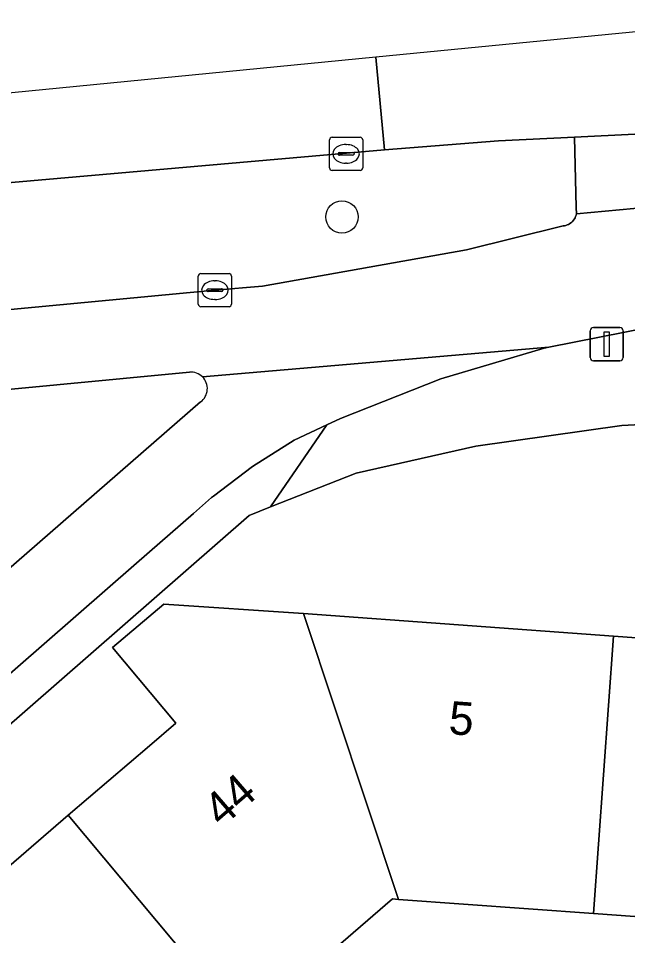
# Model space of a CAD drawing. Extents: x 160304 to 160955, y 383684 to 384161.
# Drawn here: x 160541.25 to 160559.64, y 384133.2 to 384160.88 of the extents above; entities that cross this region are included whole.
import ezdxf

# ---------------------------------------------------------------- set-up
doc = ezdxf.new("R2010")
doc.units = 0
for name, color, linetype in [('IMGEO_Boom', 7, 'Continuous'), ('IMGEO_Erf', 7, 'Continuous'), ('IMGEO_Fietspad_open', 7, 'Continuous'), ('IMGEO_Groenvoorziening', 7, 'Continuous'), ('IMGEO_Haag', 7, 'Continuous'), ('IMGEO_Kolk', 7, 'Continuous'), ('IMGEO_Lichtmast', 7, 'Continuous'), ('IMGEO_Pand', 7, 'Continuous'), ('IMGEO_Pand_nummerreeks', 7, 'Continuous'), ('IMGEO_Rijbaan_lokaal_gesloten', 7, 'Continuous'), ('IMGEO_Voetpad_open', 7, 'Continuous')]:
    doc.layers.add(name, color=color, linetype=linetype)

msp = doc.modelspace()

# ---------------------------------------------------------------- linework, layer by layer
at = {"layer": 'IMGEO_Boom'}
msp.add_circle((160551.016, 384154.889), 0.489, dxfattribs=at)
at = {"layer": 'IMGEO_Erf'}
for points in [[(160563.905, 384148.825), (160559.462, 384148.597), (160555.057, 384147.972), (160551.448, 384147.155), (160548.855, 384146.134), (160548.216, 384145.882), (160534.901, 384134.253), (160534.556, 384133.899), (160534.244, 384133.516), (160533.967, 384133.107), (160533.728, 384132.674), (160533.529, 384132.222), (160533.37, 384131.754), (160533.255, 384131.273), (160533.182, 384130.784), (160533.173, 384130.684), (160530.921, 384098.428)], [(160533.258, 384098.425), (160533.684, 384104.304), (160534.096, 384109.976), (160534.507, 384115.643), (160534.918, 384121.312), (160535.658, 384130.704), (160542.752, 384136.829), (160545.202, 384138.927), (160546.003, 384139.613), (160544.086, 384141.892), (160545.639, 384143.198), (160549.86, 384142.916), (160559.216, 384142.237), (160564.899, 384141.825)], [(160564.295, 384133.45), (160558.615, 384133.862), (160552.723, 384134.289), (160552.545, 384134.302), (160548.084, 384130.45), (160543.616, 384126.592), (160543.136, 384120.655), (160542.725, 384114.987), (160545.913, 384114.756), (160545.503, 384109.097), (160546.387, 384109.033), (160546.147, 384105.723), (160542.074, 384106.018), (160541.903, 384103.658), (160541.504, 384098.152)]]:
    msp.add_lwpolyline(points, dxfattribs=at)
at = {"layer": 'IMGEO_Fietspad_open'}
for points in [[(160561.563, 384155.305), (160558.095, 384154.984), (160558.084, 384154.94), (160558.07, 384154.901), (160558.053, 384154.864), (160558.033, 384154.828), (160558.01, 384154.794), (160557.984, 384154.763), (160557.955, 384154.734), (160557.923, 384154.708), (160557.89, 384154.684), (160557.854, 384154.664), (160557.817, 384154.647), (160557.778, 384154.633), (160557.738, 384154.623), (160557.698, 384154.617), (160557.657, 384154.614), (160554.776, 384153.901), (160548.621, 384152.802), (160547.181, 384152.679), (160508.78, 384149.051)], [(160546.806, 384150.059), (160557.264, 384150.954), (160560.321, 384151.564), (160566.689, 384152.042)], [(160547.082, 384146.416), (160547.136, 384146.461), (160548.319, 384147.36), (160549.578, 384148.15), (160550.555, 384148.612), (160550.969, 384148.808), (160554, 384150.005), (160557.125, 384150.926), (160557.264, 384150.954), (160546.806, 384150.059)], [(160509.91, 384146.721), (160509.934, 384146.724), (160546.418, 384150.201)], [(160546.75, 384149.308), (160539.384, 384142.903), (160535.894, 384139.821), (160537.481, 384138.035), (160544.813, 384144.436), (160546.533, 384145.937), (160547.082, 384146.416)]]:
    msp.add_lwpolyline(points, dxfattribs=at)
for centre, radius, start, end in [((160546.46, 384149.715), 0.488, 44.8556, 94.9413), ((160546.459, 384149.707), 0.494, 306.0545, 45.4165)]:
    msp.add_arc(centre, radius, start, end, dxfattribs=at)
at = {"layer": 'IMGEO_Groenvoorziening'}
for points in [[(160508.78, 384149.051), (160547.181, 384152.679), (160548.621, 384152.802), (160554.776, 384153.901), (160557.657, 384154.614), (160557.698, 384154.617), (160557.738, 384154.623), (160557.778, 384154.633), (160557.817, 384154.647), (160557.854, 384154.664), (160557.89, 384154.684), (160557.923, 384154.708), (160557.955, 384154.734), (160557.984, 384154.763), (160558.01, 384154.794), (160558.033, 384154.828), (160558.053, 384154.864), (160558.07, 384154.901), (160558.084, 384154.94), (160558.095, 384154.984), (160558.091, 384155.173), (160558.033, 384157.298), (160555.741, 384157.19), (160552.296, 384156.916), (160540.226, 384155.853)], [(160546.418, 384150.201), (160509.934, 384146.724), (160509.91, 384146.721)], [(160536.119, 384146.661), (160539.384, 384142.903), (160546.75, 384149.308)]]:
    msp.add_lwpolyline(points, dxfattribs=at)
for centre, radius, start, end in [((160546.46, 384149.715), 0.488, 44.8556, 94.9413), ((160546.459, 384149.707), 0.494, 306.0545, 45.4165)]:
    msp.add_arc(centre, radius, start, end, dxfattribs=at)
at = {"layer": 'IMGEO_Haag'}
msp.add_lwpolyline([(160508.78, 384149.051), (160547.181, 384152.679), (160548.621, 384152.802), (160554.776, 384153.901), (160557.657, 384154.614), (160557.698, 384154.617), (160557.738, 384154.623), (160557.778, 384154.633), (160557.817, 384154.647), (160557.854, 384154.664), (160557.89, 384154.684), (160557.923, 384154.708), (160557.955, 384154.734), (160557.984, 384154.763), (160558.01, 384154.794), (160558.033, 384154.828), (160558.053, 384154.864), (160558.07, 384154.901), (160558.084, 384154.94), (160558.095, 384154.984), (160558.091, 384155.173), (160558.033, 384157.298), (160555.741, 384157.19), (160552.296, 384156.916), (160540.226, 384155.853)], dxfattribs=at)
at = {"layer": 'IMGEO_Kolk'}
for p, q in [((160550.641, 384156.367), (160550.641, 384157.219)), ((160550.716, 384157.293), (160551.568, 384157.293)), ((160551.642, 384157.219), (160551.642, 384156.367)), ((160551.129, 384157.073), (160551.154, 384157.073)), ((160550.9, 384156.787), (160550.9, 384156.799)), ((160551.338, 384156.75), (160550.94, 384156.75)), ((160550.943, 384156.836), (160551.341, 384156.836)), ((160551.384, 384156.799), (160551.384, 384156.787)), ((160551.152, 384156.513), (160551.127, 384156.513)), ((160551.568, 384156.293), (160550.716, 384156.293)), ((160546.68, 384152.253), (160546.68, 384153.105)), ((160546.755, 384153.179), (160547.607, 384153.179)), ((160547.681, 384153.105), (160547.681, 384152.253)), ((160547.168, 384152.959), (160547.193, 384152.959)), ((160546.939, 384152.673), (160546.939, 384152.685)), ((160547.377, 384152.636), (160546.979, 384152.636)), ((160546.982, 384152.722), (160547.38, 384152.722)), ((160547.423, 384152.685), (160547.423, 384152.673)), ((160547.607, 384152.179), (160546.755, 384152.179)), ((160547.191, 384152.399), (160547.166, 384152.399))]:
    msp.add_line(p, q, dxfattribs=at)
for points in [[(160550.641, 384156.367), (160550.641, 384157.219)], [(160550.716, 384157.293), (160551.568, 384157.293)], [(160551.642, 384157.219), (160551.642, 384156.367)], [(160551.568, 384156.293), (160550.716, 384156.293)], [(160546.68, 384152.253), (160546.68, 384153.105)], [(160546.755, 384153.179), (160547.607, 384153.179)], [(160547.681, 384153.105), (160547.681, 384152.253)], [(160547.607, 384152.179), (160546.755, 384152.179)]]:
    msp.add_lwpolyline(points, dxfattribs=at)
for centre, radius, start, end in [((160550.718, 384157.217), 0.0765, 91.552, 178.448), ((160550.718, 384157.217), 0.0765, 91.552, 178.448), ((160551.566, 384157.217), 0.0765, 1.552, 88.448), ((160551.566, 384157.217), 0.0765, 1.552, 88.448), ((160550.94, 384156.796), 0.0403, 85.8775, 175.7526), ((160550.937, 384156.786), 0.0366, 178.938, 274.7102), ((160551.341, 384156.793), 0.043, 264.8664, 352.4533), ((160551.345, 384156.798), 0.0386, 1.7309, 96.639), ((160550.718, 384156.369), 0.0765, 181.552, 268.448), ((160550.718, 384156.369), 0.0765, 181.552, 268.448), ((160551.566, 384156.369), 0.0765, 271.552, 358.448), ((160551.566, 384156.369), 0.0765, 271.552, 358.448), ((160546.757, 384153.103), 0.0765, 91.552, 178.448), ((160546.757, 384153.103), 0.0765, 91.552, 178.448), ((160547.605, 384153.103), 0.0765, 1.552, 88.448), ((160547.605, 384153.103), 0.0765, 1.552, 88.448), ((160546.979, 384152.682), 0.0403, 85.8775, 175.7526), ((160546.976, 384152.672), 0.0366, 178.938, 274.7102), ((160547.38, 384152.679), 0.043, 264.8664, 352.4533), ((160547.384, 384152.684), 0.0386, 1.7309, 96.639), ((160546.757, 384152.255), 0.0765, 181.552, 268.448), ((160546.757, 384152.255), 0.0765, 181.552, 268.448), ((160547.605, 384152.255), 0.0765, 271.552, 358.448), ((160547.605, 384152.255), 0.0765, 271.552, 358.448)]:
    msp.add_arc(centre, radius, start, end, dxfattribs=at)
for centre, major_axis, ratio, start_param, end_param in [((160551.128, 384156.793), (-0.387, 0.002), 0.722429, 4.712389, 7.853982), ((160551.153, 384156.793), (-0.39, 0.002), 0.717154, 1.570796, 4.712389), ((160547.167, 384152.679), (-0.387, 0.002), 0.722429, 4.712389, 7.853982), ((160547.192, 384152.679), (-0.39, 0.002), 0.717154, 1.570796, 4.712389)]:
    msp.add_ellipse(centre, major_axis=major_axis, ratio=ratio, start_param=start_param, end_param=end_param, dxfattribs=at)
at = {"layer": 'IMGEO_Lichtmast'}
for p, q in [((160558.513, 384150.649), (160558.513, 384151.449)), ((160558.513, 384151.449), (160558.513, 384150.649)), ((160558.613, 384151.549), (160559.403, 384151.549)), ((160559.403, 384151.549), (160558.613, 384151.549)), ((160559.503, 384151.449), (160559.503, 384150.649)), ((160559.503, 384150.649), (160559.503, 384151.449)), ((160559.403, 384150.549), (160558.613, 384150.549)), ((160558.613, 384150.549), (160559.403, 384150.549))]:
    msp.add_line(p, q, dxfattribs=at)
msp.add_lwpolyline([(160558.933, 384151.424), (160559.083, 384151.424), (160559.083, 384150.674), (160558.933, 384150.674), (160558.933, 384151.424)], dxfattribs=at)
for centre, start, end in [((160558.613, 384151.449), 90, 180), ((160558.613, 384151.449), 90, 180), ((160559.403, 384151.449), 0, 90), ((160559.403, 384151.449), 360, 90), ((160558.613, 384150.649), 180, 270), ((160558.613, 384150.649), 180, 270), ((160559.403, 384150.649), 270, 0), ((160559.403, 384150.649), 270, 0)]:
    msp.add_arc(centre, 0.1, start, end, dxfattribs=at)
at = {"layer": 'IMGEO_Pand'}
for points in [[(160549.86, 384142.916), (160545.639, 384143.198), (160544.086, 384141.892), (160546.003, 384139.613), (160545.202, 384138.927), (160542.752, 384136.829), (160548.084, 384130.45), (160552.545, 384134.302), (160552.723, 384134.289)], [(160559.216, 384142.237), (160549.86, 384142.916), (160552.723, 384134.289), (160558.615, 384133.862)], [(160559.216, 384142.237), (160558.615, 384133.862), (160564.295, 384133.45), (160564.899, 384141.825)], [(160543.616, 384126.592), (160548.084, 384130.45), (160542.752, 384136.829), (160535.658, 384130.704)]]:
    msp.add_lwpolyline(points, close=True, dxfattribs=at)
at = {"layer": 'IMGEO_Rijbaan_lokaal_gesloten'}
msp.add_lwpolyline([(160552.039, 384159.709), (160552.296, 384156.916), (160555.741, 384157.19), (160558.033, 384157.298), (160559.854, 384157.383), (160561.015, 384157.339), (160564.155, 384157.219), (160564.02, 384160.883)], close=True, dxfattribs=at)
msp.add_lwpolyline([(160552.039, 384159.709), (160540.013, 384158.53), (160516.834, 384155.497), (160517.165, 384153.325), (160517.57, 384153.373), (160531.454, 384154.952), (160540.226, 384155.853), (160552.296, 384156.916), (160552.039, 384159.709)], dxfattribs=at)
at = {"layer": 'IMGEO_Voetpad_open'}
msp.add_lwpolyline([(160561.015, 384157.339), (160559.854, 384157.383), (160558.033, 384157.298), (160558.091, 384155.173), (160558.095, 384154.984), (160561.563, 384155.305), (160561.521, 384155.305), (160561.476, 384155.31), (160561.432, 384155.318), (160561.389, 384155.33), (160561.347, 384155.346), (160561.306, 384155.365), (160561.267, 384155.389), (160561.231, 384155.415), (160561.197, 384155.445), (160561.166, 384155.478), (160561.138, 384155.513), (160561.113, 384155.55), (160561.092, 384155.59), (160561.074, 384155.632), (160561.06, 384155.674), (160561.05, 384155.718), (160561.044, 384155.763), (160561.042, 384155.808)], close=True, dxfattribs=at)
for points in [[(160566.689, 384152.042), (160560.321, 384151.564), (160557.264, 384150.954), (160557.125, 384150.926), (160554, 384150.005), (160550.969, 384148.808), (160550.555, 384148.612), (160548.855, 384146.134), (160551.448, 384147.155), (160555.057, 384147.972), (160559.462, 384148.597), (160563.905, 384148.825)], [(160533.967, 384133.107), (160534.244, 384133.516), (160534.556, 384133.899), (160534.901, 384134.253), (160548.216, 384145.882), (160548.855, 384146.134), (160550.555, 384148.612), (160549.578, 384148.15), (160548.319, 384147.36), (160547.136, 384146.461), (160547.082, 384146.416), (160546.533, 384145.937), (160544.813, 384144.436), (160537.481, 384138.035), (160534.196, 384135.168), (160533.788, 384134.809), (160533.414, 384134.416), (160533.076, 384133.99), (160532.778, 384133.536), (160532.521, 384133.058)]]:
    msp.add_lwpolyline(points, dxfattribs=at)

# ---------------------------------------------------------------- texts
at = {"layer": 'IMGEO_Pand_nummerreeks'}
for s, rotation, p in [('5', 355.8506, (160554.219, 384139.283)), ('44', 40.8102, (160547.384, 384136.437))]:
    msp.add_text(s, height=1, rotation=rotation, dxfattribs=at).set_placement(p)

doc.saveas('drawing.dxf')
